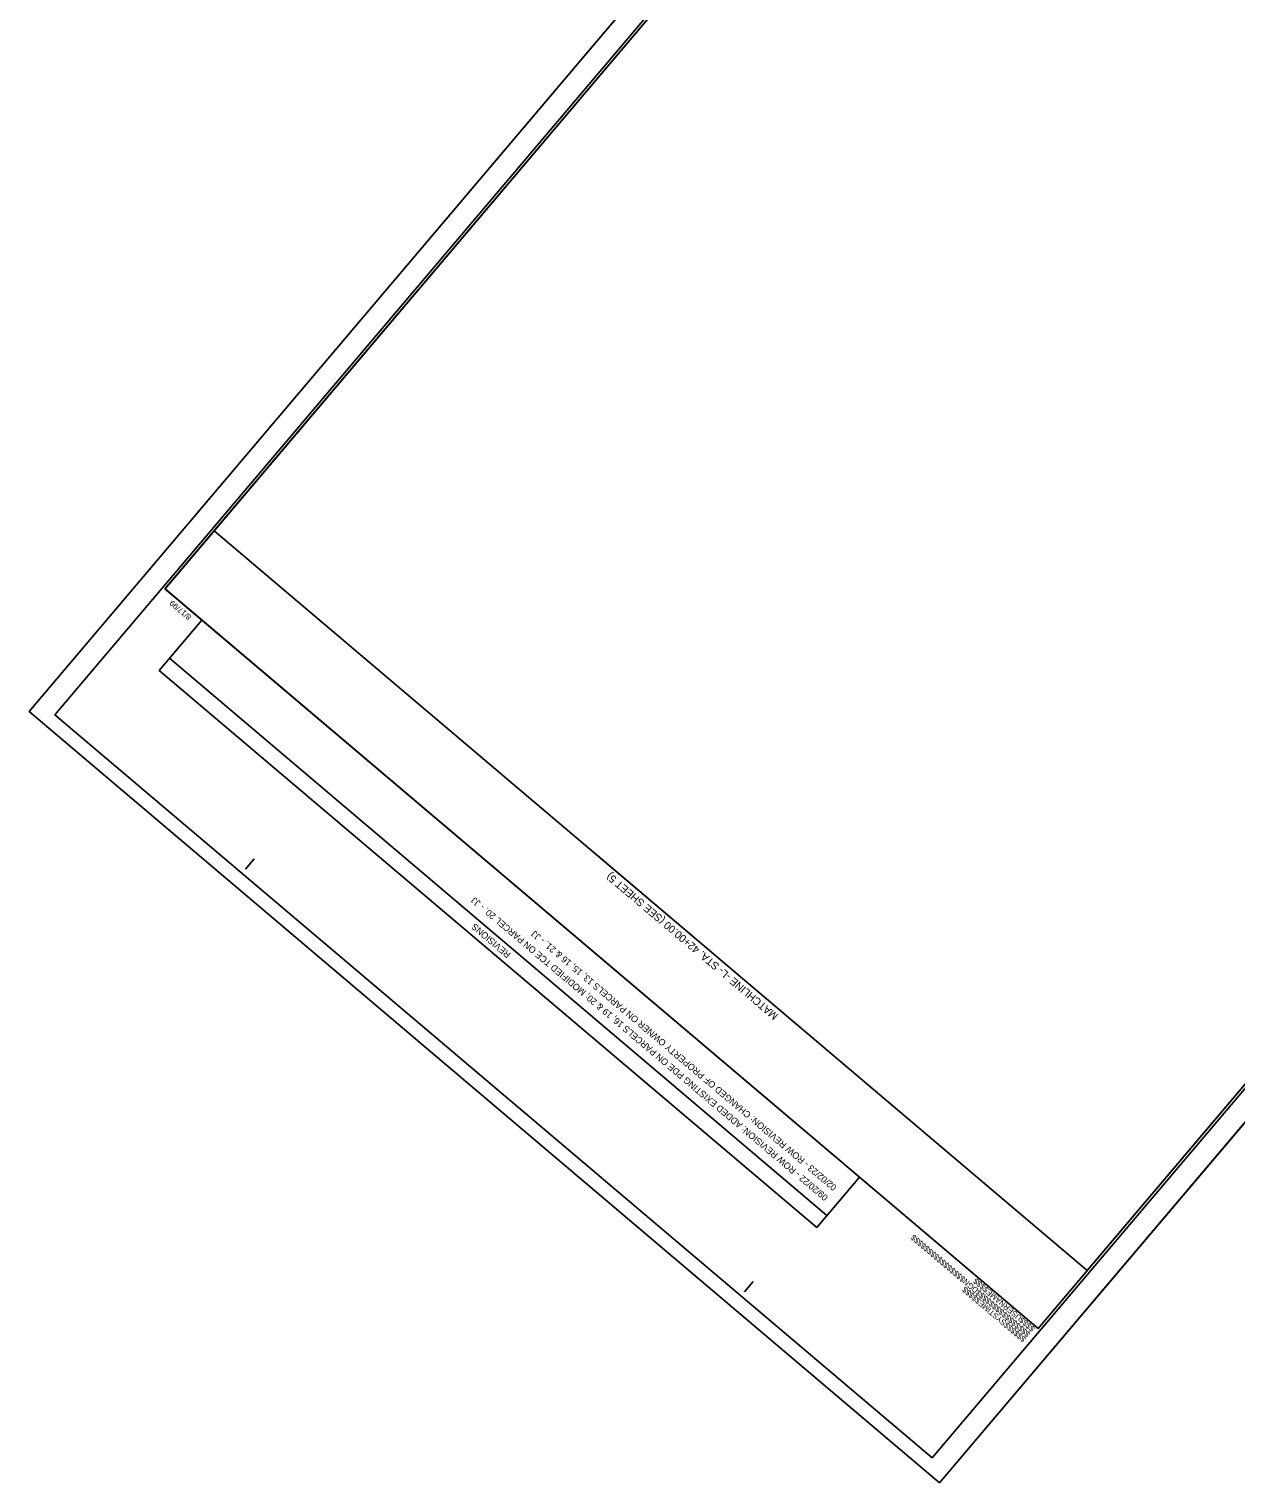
# Model space of a CAD drawing. Extents: x 1761124 to 1764673, y 421930 to 425955.
# Drawn here: x 1762749 to 1763857, y 423854 to 425188 of the extents above; entities that cross this region are included whole.
import ezdxf

# ---------------------------------------------------------------- set-up
doc = ezdxf.new("R2010")
doc.units = 0
for name, color, linetype in [('CTL Sheet Datum Description CELL', 7, 'Continuous'), ('Exist Hydro Stream or Body of Water', 7, 'Continuous'), ('Exist Other Culture Sign Post CELL', 7, 'Continuous'), ('Exist Roads Change in Surface', 7, 'Continuous'), ('Exist Roads Change in Surface Text', 7, 'Continuous'), ('Exist Roads EOP Other', 7, 'Continuous'), ('Exist Roads EOT', 7, 'Continuous'), ('Exist Roads Soil', 7, 'Continuous'), ('Exist Structure Major Deck Tunnel Box Culvert', 7, 'Continuous')]:
    doc.layers.add(name, color=color, linetype=linetype)

msp = doc.modelspace()

# ---------------------------------------------------------------- linework, layer by layer
at = {"layer": 'CTL Sheet Datum Description CELL'}
msp.add_lwpolyline([(1763720.3, 424048.8), (1764644.8, 425140), (1764016.1, 425672.7), (1763886.8, 425520), (1763714.3, 425666.1), (1762919.2, 424727.5)], close=True, dxfattribs=at)
at = {"layer": 'Exist Other Culture Sign Post CELL'}
msp.add_line((1763454.1, 424274.3), (1763271, 424429.5), dxfattribs=at)
at = {"layer": 'Exist Roads Change in Surface'}
msp.add_lwpolyline([(1763584.8, 423853.9), (1764673, 425138.5), (1763837.5, 425846.3), (1762749.3, 424561.7)], close=True, dxfattribs=at)
at = {"layer": 'Exist Roads Change in Surface Text'}
for p, q in [((1763837.5, 425846.3), (1762749.3, 424561.7)), ((1763584.8, 423853.9), (1764673, 425138.5)), ((1762749.3, 424561.7), (1763584.8, 423853.9))]:
    msp.add_line(p, q, dxfattribs=at)
at = {"layer": 'Exist Roads EOP Other'}
for p, q in [((1762874, 424674.2), (1762874, 424674.2)), ((1762947.8, 424417.1), (1762955.9, 424426.6)), ((1763405.7, 424029.3), (1763413.8, 424038.8)), ((1763675.2, 423995.5), (1763675.2, 423995.5))]:
    msp.add_line(p, q, dxfattribs=at)
for points in [[(1763843.7, 425818.8), (1762874, 424674.2), (1763675.2, 423995.5), (1764644.8, 425140)], [(1763675.2, 423995.5), (1762874.1, 424674.2), (1763714.3, 425666.1), (1763828.8, 425569.1), (1763958.1, 425721.7), (1764644.8, 425140)]]:
    msp.add_lwpolyline(points, close=True, dxfattribs=at)
at = {"layer": 'Exist Roads EOT'}
msp.add_line((1763481.4, 424099.4), (1762878.2, 424610.5), dxfattribs=at)
msp.add_lwpolyline([(1763472.1, 424088.3), (1762868.8, 424599.4), (1762907.9, 424645.6), (1763511.2, 424134.5)], close=True, dxfattribs=at)
at = {"layer": 'Exist Roads Soil'}
msp.add_lwpolyline([(1763577.9, 423876.8), (1764654.8, 425148), (1763849.8, 425829.9), (1762772.9, 424558.7)], close=True, dxfattribs=at)
at = {"layer": 'Exist Structure Major Deck Tunnel Box Culvert'}
msp.add_lwpolyline([(1762874.1, 424674.2), (1763675.2, 423995.5), (1764644.8, 425140), (1764005, 425682), (1763850.4, 425499.5), (1763689, 425636.2)], close=True, dxfattribs=at)

# ---------------------------------------------------------------- texts
at = {"layer": 'Exist Hydro Stream or Body of Water'}
msp.add_text('MATCHLINE -L- STA. 42+00.00 (SEE SHEET 5)', height=7, rotation=139.7301, dxfattribs=at).set_placement((1763437.2, 424283.4))
at = {"layer": 'Exist Roads EOP Other'}
for s, p in [('8/17/99', (1762898.8, 424649)), ('$$$$$$$$$$$$$$$$DGN$$$$$$$$$$$$$$$$', (1763668.5, 423991.2)), ('$$$$$$SYSTIME$$$$$', (1763664.6, 423986.6)), ('$$$$USERNAME$$$$', (1763672.7, 423996.2))]:
    msp.add_text(s, height=5.25, rotation=139.7301, dxfattribs=at).set_placement(p)
at = {"layer": 'Exist Roads EOT'}
for s, p in [('09/20/22 - ROW REVISION: ADDED EXISTING PDE ON PARCELS 16, 19 & 20; MODIFIED TCE ON PARCEL 20. - JJ', (1763483, 424116.7)), ('REVISIONS', (1763191.8, 424339.5)), ('02/02/23 - ROW REVISION: CHANGED OF PROPERTY OWNER ON PARCELS 13, 15, 16 & 21. - JJ ', (1763490.9, 424126))]:
    msp.add_text(s, height=6, rotation=139.7301, dxfattribs=at).set_placement(p)

doc.saveas('drawing.dxf')
